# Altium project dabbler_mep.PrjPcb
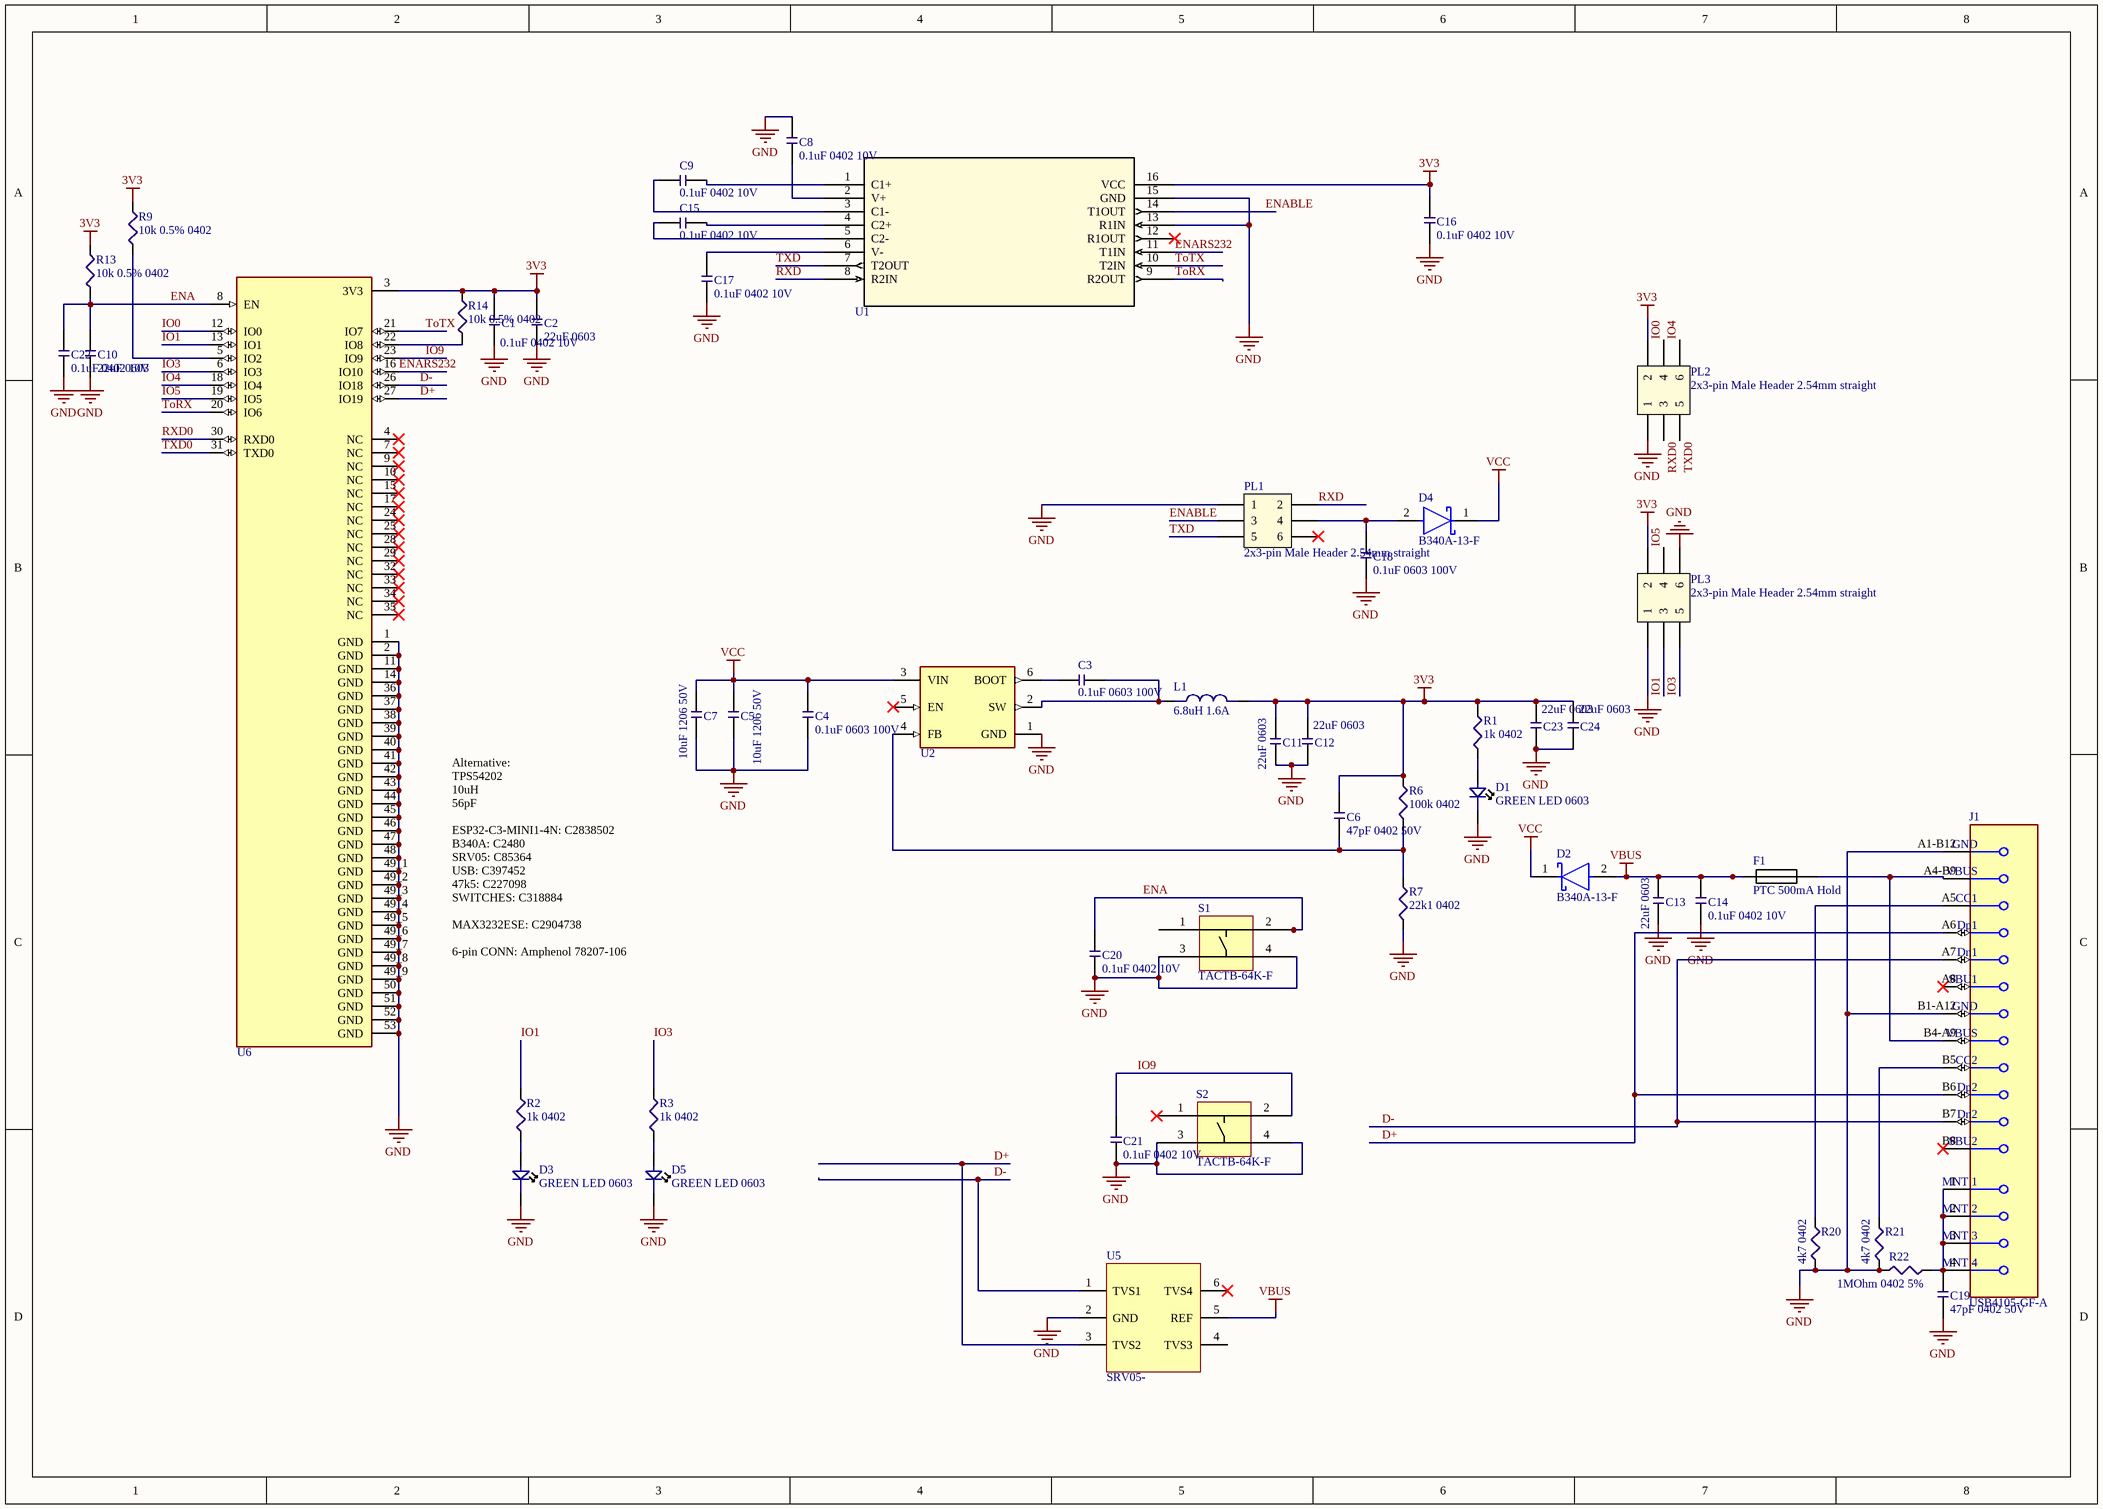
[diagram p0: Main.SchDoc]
GlobalProjectRevision: 1.0; GlobalProjectName: Dabbler MEP; GlobalDrawnBy: Mogens Groth Nicolaisen
1 sheet, 52 parts. Net scope: hierarchical (ports join the sheet entries above them; power ports are global).
Board file: dabbler_mep.PcbDoc

## Sheet Main.SchDoc: Main
size A3; DrawnBy: Mogens Groth Nicolaisen; DocumentNumber: 2; Revision: 1.0; SheetNumber: 2; SheetTotal: 7

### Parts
C1  0.1uF 0402 10V  [CAP_0402]
C2  22uF 0603  [CAP_0603]
C3  0.1uF 0603 100V  [CAP_0603]
C4  0.1uF 0603 100V  [CAP_0603]
C5  10uF 1206 50V  [CAP_1206]
C6  47pF 0402 50V  [CAP_0402]
C7  10uF 1206 50V  [CAP_1206]
C8  0.1uF 0402 10V  [CAP_0402]
C9  0.1uF 0402 10V  [CAP_0402]
C10  22uF 0603  [CAP_0603]
C11  22uF 0603  [CAP_0603]
C12  22uF 0603  [CAP_0603]
C13  22uF 0603  [CAP_0603]
C14  0.1uF 0402 10V  [CAP_0402]
C15  0.1uF 0402 10V  [CAP_0402]
C16  0.1uF 0402 10V  [CAP_0402]
C17  0.1uF 0402 10V  [CAP_0402]
C18  0.1uF 0603 100V  [CAP_0603]
C19  47pF 0402 50V  [CAP_0402]
C20  0.1uF 0402 10V  [CAP_0402]
C21  0.1uF 0402 10V  [CAP_0402]
C22  0.1uF 0402 10V  [CAP_0402]
C23  22uF 0603  [CAP_0603]
C24  22uF 0603  [CAP_0603]
D1  GREEN LED 0603  [0603 LED]
D2  B340A-13-F  [FP-SMA-MFG]
D3  GREEN LED 0603  [0603 LED]
D4  B340A-13-F  [FP-SMA-MFG]
D5  GREEN LED 0603  [0603 LED]
F1  PTC 500mA Hold  [PTC Fuse 1206]
J1  USB4105-GF-A  [FP-USB4105-GF-A-MFG]
L1  6.8uH 1.6A  [INDP4040X30N]
PL1  2x3-pin Male Header 2.54mm straight  [2x3-pin 2.54mm header]
PL2  2x3-pin Male Header 2.54mm straight  [2x3-pin 2.54mm header]
PL3  2x3-pin Male Header 2.54mm straight  [2x3-pin 2.54mm header]
R1  1k 0402  [RES_0402]
R2  1k 0402  [RES_0402]
R3  1k 0402  [RES_0402]
R6  100k 0402  [RES_0402]
R7  22k1 0402  [RES_0402]
R9  10k 0.5% 0402  [RES_0402]
R13  10k 0.5% 0402  [RES_0402]
R14  10k 0.5% 0402  [RES_0402]
R20  4k7 0402  [RES_0402]
R21  4k7 0402  [RES_0402]
R22  1MOhm 0402 5%  [RES_0402]
S1  TACTB-64K-F  [TACTB-64K-F]
S2  TACTB-64K-F  [TACTB-64K-F]
U1  MAX3232ESE  [21-0041_S16+1_MXM-M]  (value not drawn)
U2  TPS54302DDCR  [FP-DDC0006A-IPC_A]  (value not drawn)
U5  SRV05-  [SOT95P280X145-6N]
U6  ESP32-C3-MINI-1-N4  [ESP32-C3-MINI-1-N4-Footprint-1]  (value not drawn)

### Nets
3V3: C1.2 C2.2 C6.2 C11.2 C12.2 C16.2 C23.2 C24.2 L1.2 PL2.2 PL3.2 R1.2 R6.2 R9.2 R13.2 R14.2 U1.16(VCC) U6.3(3V3)
GND: C1.1 C2.1 C4.1 C5.1 C7.1 C8.2 C10.1 C11.1 C12.1 C13.1 C14.1 C16.1 C17.1 C18.1 C19.1 C20.1 C21.1 C22.2 C23.1 C24.1 D1.2 D3.2 D5.2 J1.A1-B12(GND) J1.B1-A12(GND) PL1.1 PL2.1 PL3.1 PL3.6 R7.1 R20.1 R21.1 R22.1 S1.3 S1.4 S2.3 S2.4 U1.13(R1IN) U1.15(GND) U2.1(GND) U5.2(GND) U6.1(GND) U6.2(GND) U6.11(GND) U6.14(GND) U6.36(GND) U6.37(GND) U6.38(GND) U6.39(GND) U6.40(GND) U6.41(GND) U6.42(GND) U6.43(GND) U6.44(GND) U6.45(GND) U6.46(GND) U6.47(GND) U6.48(GND) U6.49_1(GND) U6.49_2(GND) U6.49_3(GND) U6.49_4(GND) U6.49_5(GND) U6.49_6(GND) U6.49_7(GND) U6.49_8(GND) U6.49_9(GND) U6.50(GND) U6.51(GND) U6.52(GND) U6.53(GND)
VBUS: C13.2 C14.2 D2.2(A) F1.1 U5.5(REF)
VCC: C4.2 C5.2 C7.2 D2.1(C) D4.1(C) U2.3(VIN)
D+: J1.A6(Dp1) J1.B6(Dp2) U5.3(TVS2) U6.27(IO19)
D-: J1.A7(Dn1) J1.B7(Dn2) U5.1(TVS1) U6.26(IO18)
ENA: C10.2 C20.2 C22.1 R13.1 S1.2 U6.8(EN)
ENABLE: PL1.3 U1.14(T1OUT)
ENARS232: U1.11(T1IN) U6.16(IO10)
IO0: PL2.4 U6.12(IO0)
IO1: PL3.3 R2.2 U6.13(IO1)
IO3: PL3.5 R3.2 U6.6(IO3)
IO4: PL2.6 U6.18(IO4)
IO5: PL3.4 U6.19(IO5)
IO9: C21.2 S2.2 U6.23(IO9)
RXD: PL1.2 U1.8(R2IN)
RXD0: PL2.3 U6.30(RXD0)
ToRX: U1.9(R2OUT) U6.20(IO6)
ToTX: U1.10(T2IN) U6.21(IO7)
TXD: PL1.5 U1.7(T2OUT)
TXD0: PL2.5 U6.31(TXD0)
NetC3_1: C3.1 L1.1 U2.2(SW)
NetC3_2: C3.2 U2.6(BOOT)
NetC6_1: C6.1 R6.1 R7.2 U2.4(FB)
NetC8_1: C8.1 U1.2(V+)
NetC9_1: C9.1 U1.1(C1+)
NetC9_2: C9.2 U1.3(C1-)
NetC15_1: C15.1 U1.4(C2+)
NetC15_2: C15.2 U1.5(C2-)
NetC17_2: C17.2 U1.6(V-)
NetC18_2: C18.2 D4.2(A) PL1.4
NetC19_2: C19.2 J1.1(MNT_1) J1.2(MNT_2) J1.3(MNT_3) J1.4(MNT_4) R22.2
NetD1_1: D1.1 R1.1
NetD3_1: D3.1 R2.1
NetD5_1: D5.1 R3.1
NetF1_2: F1.2 J1.A4-B9(VBUS) J1.B4-A9(VBUS)
NetJ1_A5: J1.A5(CC1) R20.2
NetJ1_B5: J1.B5(CC2) R21.2
NetR9_1: R9.1 U6.5(IO2)
NetR14_1: R14.1 U6.22(IO8)

Not connected (* = marked no-connect by the designer): J1 A8(SBU1)* B8(SBU2)*; PL1 6*; S1 1; S2 1*; U1 12(R1OUT)*; U2 5(EN)*; U5 4(TVS3) 6(TVS4)*; U6 4(NC)* 7(NC)* 9(NC)* 10(NC)* 15(NC)* 17(NC)* 24(NC)* 25(NC)* 28(NC)* 29(NC)* 32(NC)* 33(NC)* 34(NC)* 35(NC)*

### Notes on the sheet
- (near C7) Alternative:
  TPS54202
  10uH
  56pF
  ESP32-C3-MINI1-4N: C2838502
  B340A: C2480
  SRV05: C85364
  USB: C397452
  47k5: C227098
  SWITCHES: C318884
  MAX3232ESE: C2904738
  6-pin CONN: Amphenol 78207-106

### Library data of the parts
C1 C8 C9 C14-C17 C20-C22 = CMP-00101-1: 0.1uF 0402 10V X7R 10%; Value: 100 nF
C2 C10-C13 C23 C24 = CMP-00148-1: Cap Ceramic 22uF 6.3V X5R 20% SMD 0603 85C Cardboard T/R
C3 C4 C18 = CMP-00012-7: 0.1uF 10% 0603 100V X7R
C5 C7 = CMP-00030-4: 10uF 1206 50V X5R 20%; Tolerance: +/- 20%
C6 C19 = CMP-00099-1: 47pF 0402 50V X7R 5%; Tolerance: 10%
D1 D3 D5 = CMP-008-0000-1: SMD GREEN WATER CLEAR; Mfg. Part Number: APT1608SGC
D2 D4 = CMP-016-0019-1: Rectifier Diode, Schottky, 1 Phase, 1 Element, 3A, 40V V(RRM), Silicon; Capacitance: 250pF; Element Configuration: Single; Forward Voltage: 500mV; Max Forward Surge Current (Ifsm): 80A; Max Reverse Current: 500uA; Polarity: Standard
F1 = CMP-017-0001-1: PTC RESET FUSE 8V 500MA 1206; Mfg. Part Number: 0ZCJ0050FF2G
J1 = CMP-003-0034-0.0: Conn USB 2.0 Type C RCP 24 POS 0.3mm/0.5mm Solder RA SMD 24 Terminal 1 Port T/R; Gender: Receptacle; Mating Cycles: 10000; Number of Ports: 1; Shielding: Shielded
L1 = CMP-00146-1: 6.8UH ±20% 1.6A 117MΩ SMD,4.0X4.0X3.0MM POWER INDUCTORS ROHS; Mfg. Part Number: SWPA4030S6R8MT
PL1 PL3 = CMP-003-0019-0.0
PL2 = CMP-003-0019-0.0: 2x3 Positions Header Connector 0.100" (2.54mm) Through Hole Gold
R1-R3 = CMP-001-0025-3: RES SMD 1K OHM 1% 1/16W 0402; Mfg. Part Number: CRG0402F1K0
R6 = CMP-00123-1: Res General Purpose Thick Film 0402 100K Ohm 1% 1/16W ±100ppm/°C Molded SMD Paper T/R; Mfg. Part Number: RC0402FR-07100KL; Voltage: 50V; Power Rating: 63mW; Resistance: 100kR
R7 = CMP-00147-1: VISHAY - CRCW040222K1FKEDC. - D10/CRCW0402-C 100 22K1 1% ET7 E3; Resistance: 22.1kR; Max Power Dissipation: 63mW; Temperature Coefficient: 100ppm/°C
R9 R13 R14 = CMP-0001-00029-2: RES 10K OHM 0.5% 1/16W 0402; Manufacturer Part No.: RC0402DR-0710KL
R20 R21 = CMP-001-0029-3: RES SMD 4.7K OHM 1% 1/16W 0402; Mfg. Part Number: RC1005F472CS; Tolerance: 1
R22 = CMP-001-0065-1: RES SMD 1M OHM 5% 1/16W 0402; Mfg. Part Number: CR0402JC1MS001; Value: 1Mega
S1 S2 = CMP-013-0002-1: Microswitch TACT; SPST-NO; Positions:2; 0.05A/12VDC;
U1 = CMP-00180-1: MAX3232 Series 5.5 V 120 kbps Surface Mount RS-232 Transceiver - SOIC-16
U2 = CMP-00145-0.0: BUCK ADJ 3A 6SOT; Quiescent Current: 40uA; Output Type: Adjustable; Output Configuration: Positive; Number of Outputs: 1; Min Input Voltage: 4.5V; Max Input Voltage: 28V; Min Output Voltage: 596mV; Switching Frequency: 400kHz; Synchronous Rectifier: Yes
U5 = CMP-016-0020-1: SRV05 Series 4 Ch 3.5 pF 15 Vclamp Steering Diode/TVS Array Combo - SOT-23-6; Capacitance: 3.5pF; Clamping Voltage: 15V; Direction: Unidirectional; Leakage Current: 5uA; Number of Channels: 4; Number of Elements: 1; Peak Pulse Current: 5A; Peak Pulse Power: 500W; Reverse Breakdown Voltage: 6V; Reverse Standoff Voltage: 5V; Test Current: 1mA
U6 = CMP-00162-1: Bluetooth, WiFi 802.11b/g/n, Bluetooth v5.0 Transceiver Module 2.412GHz ~ 2.484GHz PCB Trace Surface Mount

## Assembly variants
Default: not fitted J1 PL2 PL2 PL3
